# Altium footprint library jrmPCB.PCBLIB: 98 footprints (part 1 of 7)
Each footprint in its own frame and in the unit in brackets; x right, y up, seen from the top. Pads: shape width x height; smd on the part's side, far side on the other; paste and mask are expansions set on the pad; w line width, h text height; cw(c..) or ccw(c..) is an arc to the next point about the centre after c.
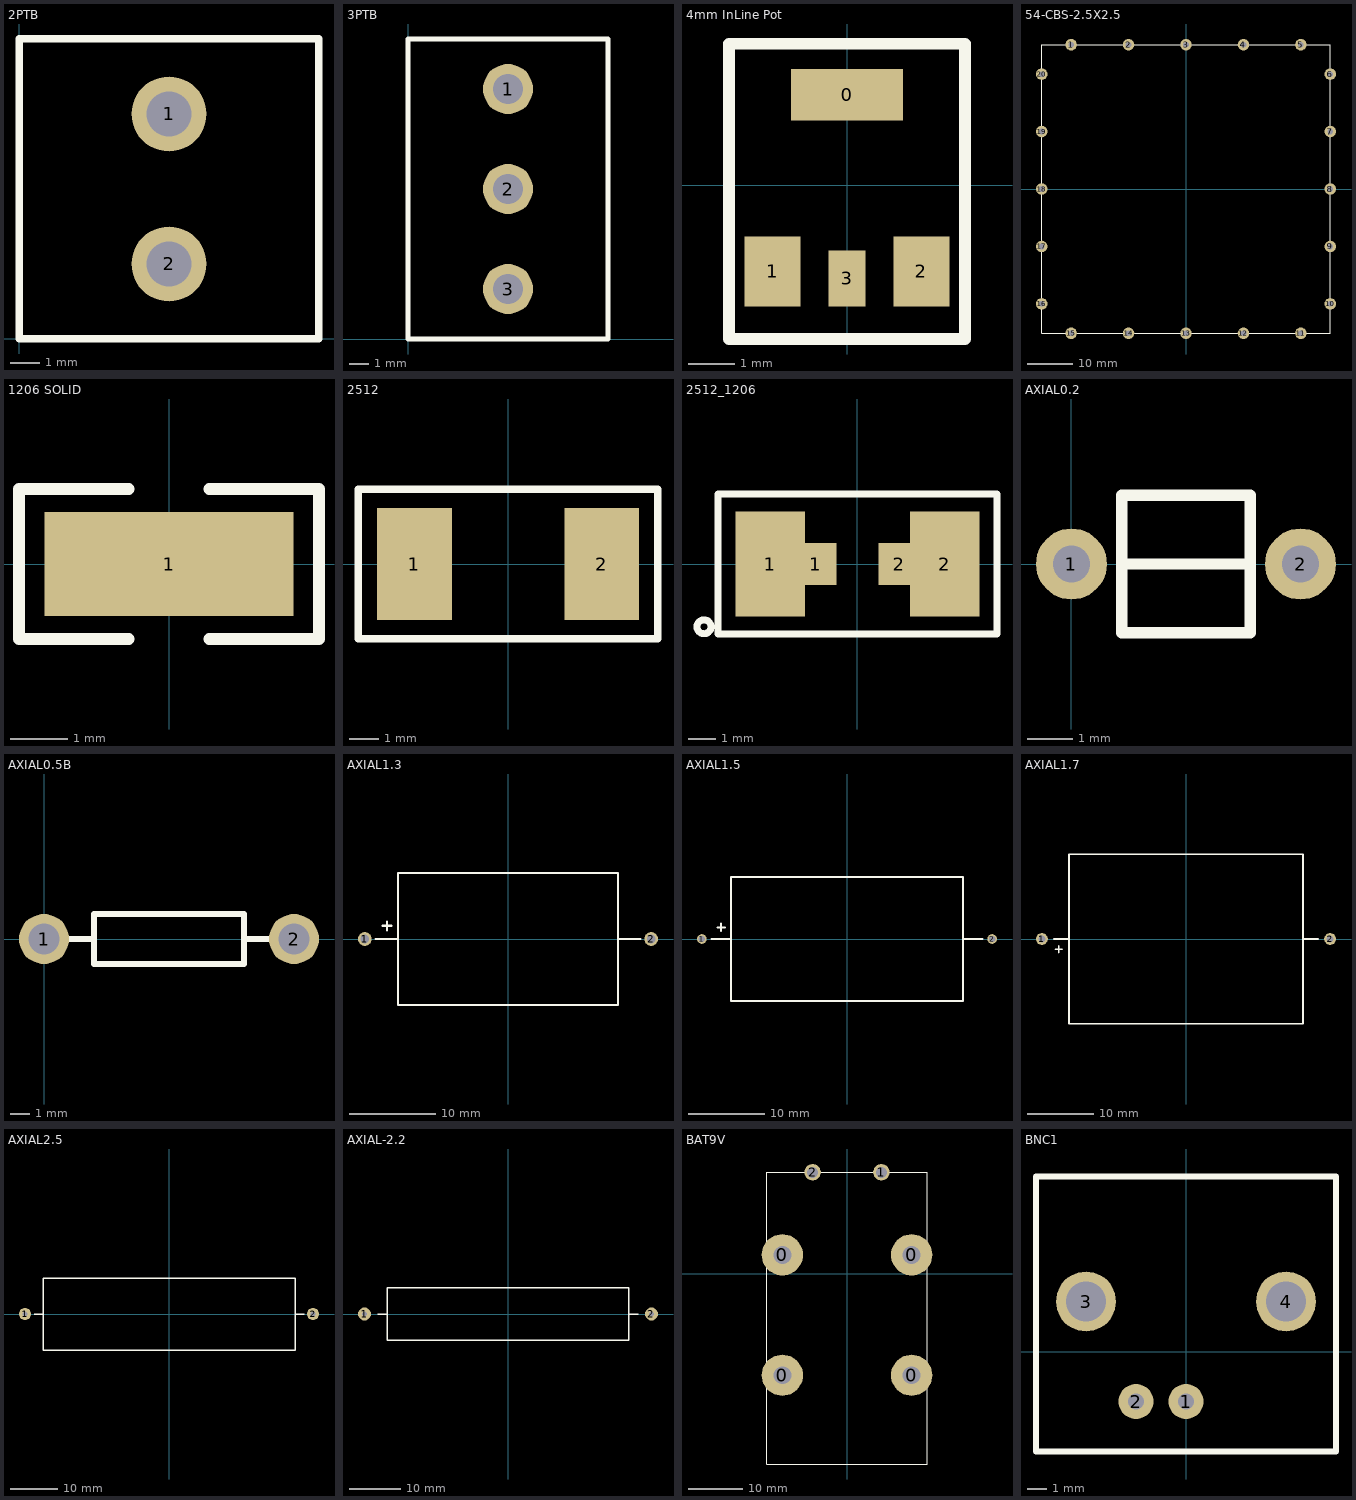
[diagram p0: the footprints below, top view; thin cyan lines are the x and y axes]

## 2PTB [mil]
pads (2):
  round 100 hole 60: 1(200,300) 2(200,100)
Top Overlay:
  lines w10: 0,0 0,400 400,400 400,0 0,0

## 3PTB [mil]
pads (3):
  round 100 hole 60: 1(200,500) 2(200,300) 3(200,100)
Top Overlay:
  lines w10: 0,0 0,600 400,600 400,0 0,0

## 4mm InLine Pot [mm]
pads (4):
  rect 2.4x1.1 smd: 0(0,1.95)
  rect 1.2x1.5 smd: 1(-1.6,-1.85) 2(1.6,-1.85)
  rect 0.8x1.2 smd: 3(0,-2)
Top Overlay:
  lines w0.254: -2.54,-3.302 -2.54,3.048 0,3.048 2.54,3.048 2.54,-3.302 0,-3.302 -2.54,-3.302

## 54-CBS-2.5X2.5 [mil] "2.5\" X 2.5\" RF Can"
height 500
pads (20):
  round 100 hole 50: 1(-1000,1256) 2(-500,1256) 3(0,1256) 4(500,1256) 5(1000,1256) 6(1256,1000) 7(1256,500) 8(1256,0) 9(1256,-500) 10(1256,-1000) 11(1000,-1256) 12(500,-1256) 13(0,-1256) 14(-500,-1256) 15(-1000,-1256) 16(-1256,-1000) 17(-1256,-500) 18(-1256,0) 19(-1256,500) 20(-1256,1000)
Top Overlay:
  lines w10: -1256,-1256 -1256,1256 1256,1256 1256,-1256 -1256,-1256

## 1206 SOLID [mil]
pads (1):
  rect 170x70.87 smd: 1(0,0)
Top Overlay:
  lines w7.87: -27.56,-51.18 -102.36,-51.18 -102.36,51.18 -27.56,51.18 ; 27.56,-51.18 102.36,-51.18 102.36,51.18 27.56,51.18

## 2512 [mil]
pads (2):
  rect 100x150 smd: 1(-125,0) 2(125,0)
Top Overlay:
  lines w10: -200,-100 200,-100 200,100 -200,100 -200,0 -200,-100

## 2512_1206 [mil] "2512 Package with pads for 1206"
pads (4):
  rect 100x150 smd: 1(-125,0) 2(125,0)
  rect 60x60 smd: 1(-60,0) 2(60,0)
Top Overlay:
  circle w10: c-220,-90 r10
  lines w10: -200,-100 200,-100 200,100 -200,100 -200,0 -200,-100

## AXIAL0.2 [mil]
pads (2):
  round 62 hole 32: 1(0,0) 2(200,0)
Top Overlay:
  lines w10: 44,0 138,0 ; 62,0 156,0 ; 156,0 156,-60 44,-60 44,60 156,60 156,0

## AXIAL0.5B [mil]
pads (2):
  round 100 hole 62: 1(0,0) 2(500,0)
Top Overlay:
  lines w12: 40,0 100,0 ; 400,0 460,0 ; 100,-50 100,50 400,50 400,-50 100,-50

## AXIAL1.3 [mil]
pads (2):
  round 62 hole 40: 1(-650,0) 2(650,0)
Top Overlay:
  lines w10: -600,0 -500,0 ; -570,60 -530,60 ; -550,40 -550,80 ; 500,0 600,0 ; -500,-300 500,-300 500,300 -500,300 -500,-300

## AXIAL1.5 [mil]
pads (2):
  round 50 hole 32: 1(-750,0) 2(750,0)
Top Overlay:
  lines w10: -700,0 -600,0 ; -670,60 -630,60 ; -650,40 -650,80 ; 600,0 700,0 ; -600,-320 -600,320 600,320 600,-320 -600,-320

## AXIAL1.7 [mil]
pads (2):
  round 70 hole 40: 1(-850,0) 2(850,0)
Top Overlay:
  lines w10: -780,0 -690,0 ; -770,-60 -730,-60 ; -750,-80 -750,-40 ; 690,0 780,0 ; -690,0 -690,500 690,500 690,-500 -690,-500 -690,0

## AXIAL2.5 [mil]
pads (2):
  round 100 hole 40: 1(-1200,0) 2(1200,0)
Top Overlay:
  lines w12: -1125,0 -1050,0 ; 1050,0 1125,0 ; -1050,-300 1050,-300 1050,300 -1050,300 -1050,-300

## AXIAL-2.2 [mil]
pads (2):
  round 100 hole 40: 1(-1100,0) 2(1100,0)
Top Overlay:
  lines w10: -1000,0 -925,0 ; 925,0 1000,0 ; -925,0 -925,-200 925,-200 925,200 -925,200 -925,0

## BAT9V [mil] "9V Battery Holder"
height 800
pads (6):
  round 300 hole 130: 0(-470,-737.5) 0(-470,137.5) 0(470,-737.5) 0(470,137.5)
  round 120 hole 80: 1(250,737.5) 2(-250,737.5)
Top Overlay:
  lines w7.87: -583,-1382.5 -583,737.5 582.5,737.5 582.5,-1382.5 -583,-1382.5

## BNC1 [mil]
pads (4):
  round 70 hole 32: 1(0,-100) 2(-100,-100)
  round 120 hole 80: 3(-200,100) 4(200,100)
Top Overlay:
  lines w12: -300,-200 300,-200 300,350 -300,350 -300,-200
